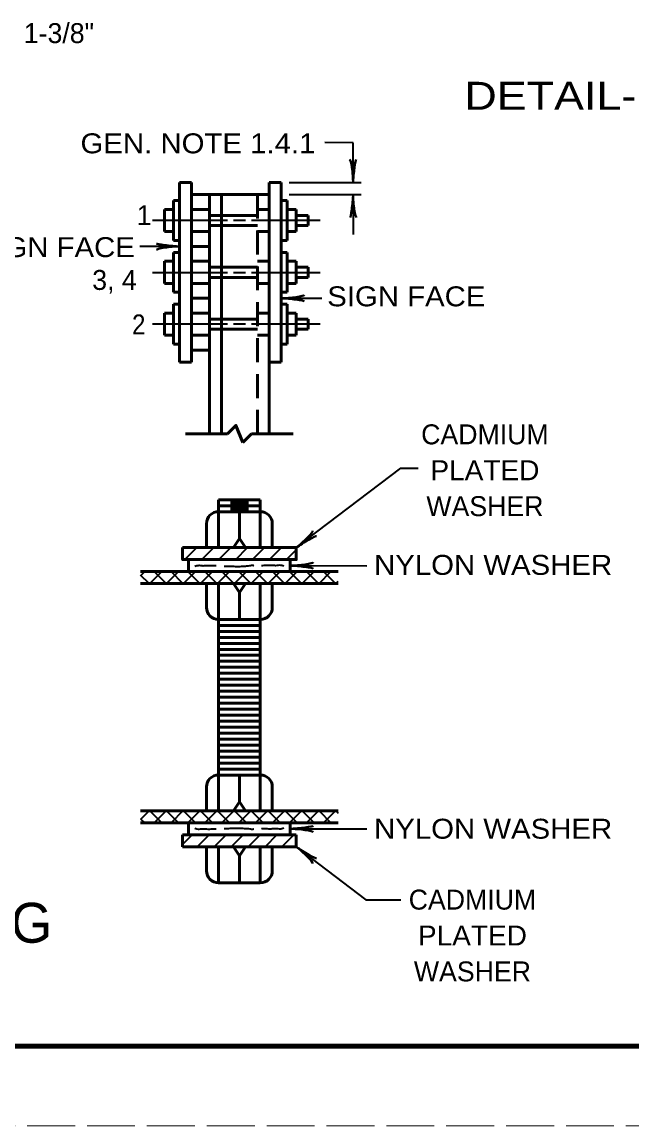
# Model space of a CAD drawing. Extents: x -41 to 639, y -374 to 66.
# Drawn here: x 377.7 to 454.1, y -374.1 to -235.7 of the extents above; entities that cross this region are included whole.
import ezdxf
from ezdxf.enums import TextEntityAlignment as Align

# ---------------------------------------------------------------- set-up
doc = ezdxf.new("R2010")
doc.units = 0
doc.linetypes.add('LONG_DASHED', pattern=[7.5, 6, -1.5])
doc.linetypes.add('MEDIUM_DASHED', pattern=[4.5, 3, -1.5])
doc.layers.add('1', color=7, linetype='Continuous', lineweight=53)
doc.layers.add('61', color=7, linetype='Continuous', lineweight=35)

msp = doc.modelspace()

# ---------------------------------------------------------------- linework, layer by layer
at = {"layer": '1', "lineweight": 35}
for p, q in [((419.132, -250.866), (415.593, -250.827)), ((419.132, -255.866), (419.132, -250.866)), ((411.132, -255.866), (420.132, -255.866)), ((411.132, -257.366), (420.132, -257.366)), ((419.132, -257.366), (419.132, -262.366)), ((403.382, -260.614), (394.007, -260.614)), ((405.632, -260.614), (404.132, -260.614)), ((415.007, -260.614), (406.382, -260.614)), ((397.382, -263.872), (392.431, -263.872)), ((394.007, -267.116), (403.382, -267.116)), ((404.132, -267.116), (405.632, -267.116)), ((406.382, -267.116), (415.007, -267.116)), ((410.132, -270.364), (415.201, -270.364)), ((403.382, -273.619), (394.007, -273.619)), ((405.632, -273.619), (404.132, -273.619)), ((415.007, -273.619), (406.382, -273.619)), ((398.055, -303.116), (399.555, -301.616)), ((400.176, -303.116), (401.676, -301.616)), ((402.298, -303.116), (403.798, -301.616)), ((404.419, -303.116), (405.919, -301.616)), ((406.54, -303.116), (408.04, -301.616)), ((408.661, -303.116), (410.161, -301.616)), ((410.783, -303.116), (412.007, -301.892)), ((411.257, -303.866), (420.867, -303.884)), ((392.507, -305.135), (393.026, -304.616)), ((393.573, -306.116), (392.507, -305.05)), ((393.647, -306.116), (395.147, -304.616)), ((395.695, -306.116), (394.195, -304.616)), ((395.768, -306.116), (397.268, -304.616)), ((397.816, -306.116), (396.316, -304.616)), ((397.89, -306.116), (399.39, -304.616)), ((399.937, -306.116), (398.437, -304.616)), ((400.011, -306.116), (401.511, -304.616)), ((402.059, -306.116), (400.559, -304.616)), ((402.132, -306.116), (403.632, -304.616)), ((404.18, -306.116), (402.68, -304.616)), ((404.254, -306.116), (405.754, -304.616)), ((406.301, -306.116), (404.801, -304.616)), ((406.375, -306.116), (407.875, -304.616)), ((408.422, -306.116), (406.922, -304.616)), ((408.496, -306.116), (409.996, -304.616)), ((410.544, -306.116), (409.044, -304.616)), ((410.618, -306.116), (412.118, -304.616)), ((412.665, -306.116), (411.165, -304.616)), ((412.739, -306.116), (414.239, -304.616)), ((414.786, -306.116), (413.286, -304.616)), ((414.86, -306.116), (416.36, -304.616)), ((416.908, -306.116), (415.408, -304.616)), ((416.982, -306.116), (417.257, -305.841)), ((393.573, -334.616), (392.507, -335.683)), ((393.647, -334.616), (395.147, -336.116)), ((395.695, -334.616), (394.195, -336.116)), ((395.768, -334.616), (397.268, -336.116)), ((397.816, -334.616), (396.316, -336.116)), ((397.89, -334.616), (399.39, -336.116)), ((399.937, -334.616), (398.437, -336.116)), ((400.011, -334.616), (401.511, -336.116)), ((402.059, -334.616), (400.559, -336.116)), ((402.132, -334.616), (403.632, -336.116)), ((404.18, -334.616), (402.68, -336.116)), ((404.254, -334.616), (405.754, -336.116)), ((406.301, -334.616), (404.801, -336.116)), ((406.375, -334.616), (407.875, -336.116)), ((408.422, -334.616), (406.922, -336.116)), ((408.496, -334.616), (409.996, -336.116)), ((410.544, -334.616), (409.044, -336.116)), ((410.618, -334.616), (412.118, -336.116)), ((412.665, -334.616), (411.165, -336.116)), ((412.739, -334.616), (414.239, -336.116)), ((414.786, -334.616), (413.286, -336.116)), ((414.86, -334.616), (416.36, -336.116)), ((416.908, -334.616), (415.408, -336.116)), ((416.982, -334.616), (417.257, -334.891)), ((392.507, -335.597), (393.026, -336.116)), ((411.257, -336.866), (420.867, -336.849)), ((398.986, -337.618), (397.763, -338.842)), ((401.108, -337.618), (399.608, -339.118)), ((403.229, -337.618), (401.729, -339.118)), ((405.35, -337.618), (403.85, -339.118)), ((407.472, -337.618), (405.972, -339.118)), ((409.593, -337.618), (408.093, -339.118)), ((411.714, -337.618), (410.214, -339.118)), ((412.007, -339.116), (420.738, -345.754)), ((420.738, -345.754), (425.125, -345.754))]:
    msp.add_line(p, q, dxfattribs=at)
at = {"layer": '1'}
for p, q in [((397.382, -255.866), (397.382, -278.366)), ((397.382, -255.866), (398.882, -255.866)), ((398.882, -255.866), (398.882, -278.366)), ((408.632, -255.866), (408.632, -287.366)), ((408.632, -255.866), (410.132, -255.866)), ((410.132, -255.866), (410.132, -278.366)), ((396.632, -258.109), (397.382, -258.109)), ((396.632, -258.109), (396.632, -263.119)), ((398.882, -257.359), (401.132, -257.359)), ((398.882, -257.366), (408.632, -257.366)), ((402.632, -257.366), (402.632, -287.366)), ((410.882, -258.109), (410.132, -258.109)), ((410.882, -258.109), (410.882, -263.119)), ((395.507, -259.234), (395.507, -261.994)), ((395.507, -259.234), (396.632, -259.234)), ((398.882, -259.234), (401.132, -259.234)), ((401.132, -259.984), (407.132, -259.984)), ((407.132, -259.234), (408.632, -259.234)), ((412.007, -259.234), (410.882, -259.234)), ((412.007, -259.234), (412.007, -261.994)), ((412.007, -259.984), (413.507, -259.984)), ((413.507, -259.984), (413.507, -261.244)), ((401.132, -261.244), (407.132, -261.244)), ((412.007, -261.244), (413.507, -261.244)), ((395.507, -261.994), (396.632, -261.994)), ((398.882, -261.994), (401.132, -261.994)), ((407.132, -261.994), (408.632, -261.994)), ((412.007, -261.994), (410.882, -261.994)), ((396.632, -263.119), (397.382, -263.119)), ((398.882, -263.861), (401.132, -263.861)), ((398.882, -263.869), (401.132, -263.869)), ((410.882, -263.119), (410.132, -263.119)), ((396.632, -264.611), (397.382, -264.611)), ((396.632, -264.611), (396.632, -269.621)), ((410.882, -264.611), (410.132, -264.611)), ((410.882, -264.611), (410.882, -269.621)), ((395.507, -265.736), (395.507, -268.496)), ((395.507, -265.736), (396.632, -265.736)), ((398.882, -265.736), (401.132, -265.736)), ((401.132, -266.486), (407.132, -266.486)), ((407.132, -265.736), (408.632, -265.736)), ((412.007, -265.736), (410.882, -265.736)), ((412.007, -265.736), (412.007, -268.496)), ((412.007, -266.486), (413.507, -266.486)), ((413.507, -266.486), (413.507, -267.746)), ((401.132, -267.746), (407.132, -267.746)), ((412.007, -267.746), (413.507, -267.746)), ((395.507, -268.496), (396.632, -268.496)), ((396.632, -269.621), (397.382, -269.621)), ((398.882, -268.496), (401.132, -268.496)), ((407.132, -268.496), (408.632, -268.496)), ((410.882, -269.621), (410.132, -269.621)), ((412.007, -268.496), (410.882, -268.496)), ((396.632, -271.114), (397.382, -271.114)), ((396.632, -271.114), (396.632, -276.124)), ((398.882, -270.364), (401.132, -270.364)), ((398.882, -270.371), (401.132, -270.371)), ((410.882, -271.114), (410.132, -271.114)), ((410.882, -271.114), (410.882, -276.124)), ((395.507, -272.239), (395.507, -274.999)), ((395.507, -272.239), (396.632, -272.239)), ((398.882, -272.239), (401.132, -272.239)), ((407.132, -272.239), (408.632, -272.239)), ((412.007, -272.239), (410.882, -272.239)), ((412.007, -272.239), (412.007, -274.999)), ((401.132, -272.989), (407.132, -272.989)), ((412.007, -272.989), (413.507, -272.989)), ((413.507, -272.989), (413.507, -274.249)), ((395.507, -274.999), (396.632, -274.999)), ((398.882, -274.999), (401.132, -274.999)), ((401.132, -274.249), (407.132, -274.249)), ((407.132, -274.999), (408.632, -274.999)), ((412.007, -274.999), (410.882, -274.999)), ((412.007, -274.249), (413.507, -274.249)), ((396.632, -276.124), (397.382, -276.124)), ((410.882, -276.124), (410.132, -276.124)), ((398.882, -276.866), (401.132, -276.866)), ((398.882, -276.874), (401.132, -276.874)), ((397.382, -278.366), (398.882, -278.366)), ((408.632, -278.366), (410.132, -278.366)), ((398.132, -287.366), (403.382, -287.366)), ((406.382, -287.366), (405.321, -288.427)), ((406.382, -287.366), (411.632, -287.366)), ((402.257, -295.616), (407.507, -295.616)), ((403.757, -295.991), (406.007, -295.991)), ((402.257, -296.366), (407.507, -296.366)), ((402.257, -297.116), (407.507, -297.116)), ((403.757, -296.741), (406.007, -296.741)), ((400.757, -298.616), (400.757, -301.616)), ((409.007, -298.616), (409.007, -301.616)), ((404.882, -300.491), (405.632, -301.616)), ((398.507, -303.116), (398.507, -304.616)), ((411.257, -303.116), (411.257, -304.616)), ((417.257, -304.616), (392.507, -304.616)), ((392.507, -306.116), (417.257, -306.116)), ((400.757, -309.116), (400.757, -306.116)), ((402.257, -310.616), (402.257, -306.116)), ((404.882, -307.241), (405.632, -306.116)), ((407.507, -310.616), (407.507, -306.116)), ((409.007, -309.116), (409.007, -306.116)), ((402.257, -310.616), (407.507, -310.616)), ((402.257, -310.616), (402.257, -330.116)), ((407.507, -310.616), (407.507, -330.116)), ((402.257, -311.366), (407.507, -311.366)), ((402.257, -312.116), (407.507, -312.116)), ((402.257, -312.866), (407.507, -312.866)), ((402.257, -313.616), (407.507, -313.616)), ((402.257, -314.366), (407.507, -314.366)), ((402.257, -315.116), (407.507, -315.116)), ((402.257, -315.866), (407.507, -315.866)), ((402.257, -316.616), (407.507, -316.616)), ((402.257, -317.366), (407.507, -317.366)), ((402.257, -318.116), (407.507, -318.116)), ((402.257, -318.866), (407.507, -318.866)), ((402.257, -319.616), (407.507, -319.616)), ((402.257, -320.366), (407.507, -320.366)), ((402.257, -321.116), (407.507, -321.116)), ((402.257, -321.866), (407.507, -321.866)), ((402.257, -322.616), (407.507, -322.616)), ((402.257, -323.366), (407.507, -323.366)), ((402.257, -324.116), (407.507, -324.116)), ((402.257, -324.866), (407.507, -324.866)), ((402.257, -325.616), (407.507, -325.616)), ((402.257, -326.366), (407.507, -326.366)), ((402.257, -327.116), (407.507, -327.116)), ((402.257, -327.866), (407.507, -327.866)), ((402.257, -328.616), (407.507, -328.616)), ((402.257, -329.366), (407.507, -329.366)), ((402.257, -330.116), (407.507, -330.116)), ((402.257, -330.116), (402.257, -334.616)), ((407.507, -330.116), (407.507, -334.616)), ((400.757, -331.616), (400.757, -334.616)), ((409.007, -331.616), (409.007, -334.616)), ((417.257, -334.616), (392.507, -334.616)), ((404.882, -333.491), (405.632, -334.616)), ((417.257, -336.116), (392.507, -336.116)), ((398.507, -337.616), (398.507, -336.116)), ((411.257, -337.616), (411.257, -336.116)), ((397.757, -337.616), (412.007, -337.616)), ((397.757, -339.116), (397.757, -337.616)), ((412.007, -339.116), (412.007, -337.616)), ((400.757, -342.116), (400.757, -339.116)), ((402.257, -343.616), (402.257, -339.116)), ((404.882, -340.241), (404.132, -339.116)), ((404.882, -340.241), (405.632, -339.116)), ((404.882, -343.616), (404.882, -340.241)), ((407.507, -343.616), (407.507, -339.116)), ((409.007, -342.116), (409.007, -339.116)), ((402.257, -343.616), (407.507, -343.616))]:
    msp.add_line(p, q, dxfattribs=at)
at = {"layer": '1', "linetype": 'MEDIUM_DASHED'}
msp.add_line((407.132, -257.366), (407.132, -287.366), dxfattribs=at)
at = {"layer": '1'}
for points in [[(401.132, -257.366), (401.132, -263.861), (401.132, -270.371), (401.132, -276.866), (401.132, -287.366)], [(403.382, -287.366), (404.442, -286.305), (405.321, -288.427)], [(402.257, -295.616), (402.257, -297.116), (402.257, -301.616)], [(407.507, -295.616), (407.507, -297.116), (407.507, -301.616)], [(404.882, -297.116), (404.882, -300.491), (404.132, -301.616)], [(404.882, -310.616), (404.882, -307.241), (404.132, -306.116)], [(404.882, -330.116), (404.882, -333.491), (404.132, -334.616)], [(397.757, -339.116), (404.132, -339.116), (412.007, -339.116)]]:
    msp.add_lwpolyline(points, dxfattribs=at)
at = {"layer": '1', "lineweight": 35}
msp.add_lwpolyline([(412.007, -301.616), (425.113, -291.651), (427.276, -291.651)], dxfattribs=at)
at = {"layer": '1'}
msp.add_lwpolyline([(397.757, -301.616), (397.757, -303.116), (412.007, -303.116), (412.007, -301.616), (404.132, -301.616)], close=True, dxfattribs=at)
for centre, start, end in [((402.257, -298.616), 90, 180), ((407.507, -298.616), 0, 90), ((402.257, -309.116), 180, 270), ((407.507, -309.116), 270, 0), ((402.257, -331.616), 90, 180), ((407.507, -331.616), 0, 90), ((402.257, -342.116), 180, 270), ((407.507, -342.116), 270, 0)]:
    msp.add_arc(centre, 1.5, start, end, dxfattribs=at)
at = {"layer": '1', "lineweight": 40}
for centre, major_axis, ratio, start_param, end_param in [((418.855, -254.775), (0.156, -1.786), 0.122415, 0.8963533, 3.1415927), ((418.855, -254.775), (0.156, -1.786), 0.122415, 0.8963533, 3.1415927), ((419.343, -254.746), (-0.176, -1.756), 0.07063, 3.1407148, 5.41811), ((419.343, -254.746), (-0.176, -1.756), 0.07063, 3.1407148, 5.41811), ((418.92, -258.487), (0.176, 1.756), 0.07063, 3.1407148, 5.41811), ((419.408, -258.457), (-0.156, 1.786), 0.122415, 0.8963533, 3.1415927), ((396.29, -264.148), (1.786, 0.156), 0.122415, 0.8963533, 3.1415927), ((396.29, -264.148), (1.786, 0.156), 0.122415, 0.8963533, 3.1415927), ((396.261, -263.66), (1.756, -0.176), 0.07063, 3.1407148, 5.41811), ((396.261, -263.66), (1.756, -0.176), 0.07063, 3.1407148, 5.41811), ((411.252, -270.576), (-1.756, 0.176), 0.07063, 3.1407148, 5.41811), ((411.223, -270.088), (-1.786, -0.156), 0.122415, 0.8963533, 3.1415927), ((412.708, -300.736), (-1.327, -1.205), 0.122415, 0.8963533, 3.1415927), ((412.708, -300.736), (-1.327, -1.205), 0.122415, 0.8963533, 3.1415927), ((413.027, -301.106), (-1.505, -0.923), 0.07063, 3.1407148, 5.41811), ((413.027, -301.106), (-1.505, -0.923), 0.07063, 3.1407148, 5.41811), ((412.348, -303.592), (-1.786, -0.153), 0.122415, 0.8963533, 3.1415927), ((412.377, -304.08), (-1.756, 0.179), 0.07063, 3.1407148, 5.41811), ((412.348, -337.14), (-1.786, 0.153), 0.122415, 3.1415927, 5.386832), ((412.377, -336.653), (-1.756, -0.179), 0.07063, 0.8650754, 3.1424706), ((412.708, -339.997), (-1.327, 1.205), 0.122415, 3.1415927, 5.386832), ((412.708, -339.997), (-1.327, 1.205), 0.122415, 3.1415927, 5.386832), ((413.027, -339.626), (-1.505, 0.923), 0.07063, 0.8650754, 3.1424706), ((413.027, -339.626), (-1.505, 0.923), 0.07063, 0.8650754, 3.1424706)]:
    msp.add_ellipse(centre, major_axis=major_axis, ratio=ratio, start_param=start_param, end_param=end_param, dxfattribs=at)
at = {"layer": '1', "lineweight": 35}
for points in [[(399.306, -303.937), (399.841, -303.836), (400.202, -303.879), (400.766, -303.85), (401.345, -303.85), (401.822, -303.865), (401.958, -303.877)], [(402.994, -303.923), (403.731, -303.937), (404.353, -303.966), (404.961, -303.966), (405.655, -303.923), (406.176, -303.879), (406.61, -303.836), (406.711, -303.879)], [(410.458, -303.937), (409.922, -303.836), (409.561, -303.879), (408.997, -303.85), (408.418, -303.85), (407.941, -303.865), (407.638, -303.902)], [(399.306, -336.795), (399.841, -336.897), (400.202, -336.853), (400.766, -336.882), (401.345, -336.882), (401.822, -336.868), (401.958, -336.855)], [(402.994, -336.81), (403.731, -336.795), (404.353, -336.766), (404.961, -336.766), (405.655, -336.81), (406.176, -336.853), (406.61, -336.897), (406.711, -336.853)], [(410.458, -336.795), (409.922, -336.897), (409.561, -336.853), (408.997, -336.882), (408.418, -336.882), (407.941, -336.868), (407.638, -336.83)]]:
    msp.add_spline(points, degree=3, dxfattribs=at)
at = {"layer": '61', "lineweight": 158}
msp.add_line((628.362, -364.098), (-10.698, -364.078), dxfattribs=at)
at = {"layer": '61', "linetype": 'LONG_DASHED', "lineweight": 13}
msp.add_line((639.302, -374.078), (-40.758, -374.098), dxfattribs=at)

# ---------------------------------------------------------------- texts
at = {"layer": '1'}
for s, height, p in [('1-3/8"', 2.5, (377.873, -238.383)), ('1', 2.5, (392.021, -261.199)), ('3, 4', 2.5, (386.446, -269.319)), ('BACK-TO-BACK MOUNTING', 5, (293.019, -351.137))]:
    msp.add_text(s, height=height, dxfattribs=at).set_placement(p)
for s, height, width, p in [('DETAIL-BOLT 4', 3.5, 1.2, (433.073, -246.737)), ('GEN. NOTE 1.4.1', 2.5, 1.1, (384.979, -252.197)), ('SIGN FACE', 2.5, 1.1, (371.971, -265.21)), ('SIGN FACE', 2.5, 1.1, (415.887, -271.374)), ('2', 2.5, 0.9, (391.435, -274.896)), ('NYLON WASHER', 2.5, 1.1, (421.755, -305.031)), ('NYLON WASHER', 2.5, 1.1, (421.755, -338.101))]:
    msp.add_text(s, height=height, dxfattribs=dict(at, width=width)).set_placement(p)
for s, p in [('CADMIUM', (435.644, -288.671)), ('WASHER', (435.644, -297.671)), ('CADMIUM', (434.079, -346.984)), ('WASHER', (434.079, -355.984))]:
    msp.add_text(s, height=2.5, dxfattribs=at).set_placement(p, align=Align.CENTER)
at = {"layer": '1', "width": 1.05}
for p in [(435.644, -293.171), (434.079, -351.484)]:
    msp.add_text('PLATED', height=2.5, dxfattribs=at).set_placement(p, align=Align.CENTER)

doc.saveas('drawing.dxf')
